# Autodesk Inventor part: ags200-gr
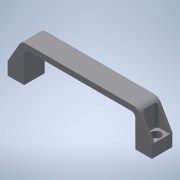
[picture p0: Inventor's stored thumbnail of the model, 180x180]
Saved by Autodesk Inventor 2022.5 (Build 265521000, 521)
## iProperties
Created: 2016-12
Part Number: ags200-gr
Material: 一般
Document SubType Name: Modeling
Designer: imaocorp
Density: 1 g/cm^3
Appearance: 既定
Author: imaocorp
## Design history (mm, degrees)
node "ags200-gr.x_t1"
node "ags200-gr"
node "Base1"
